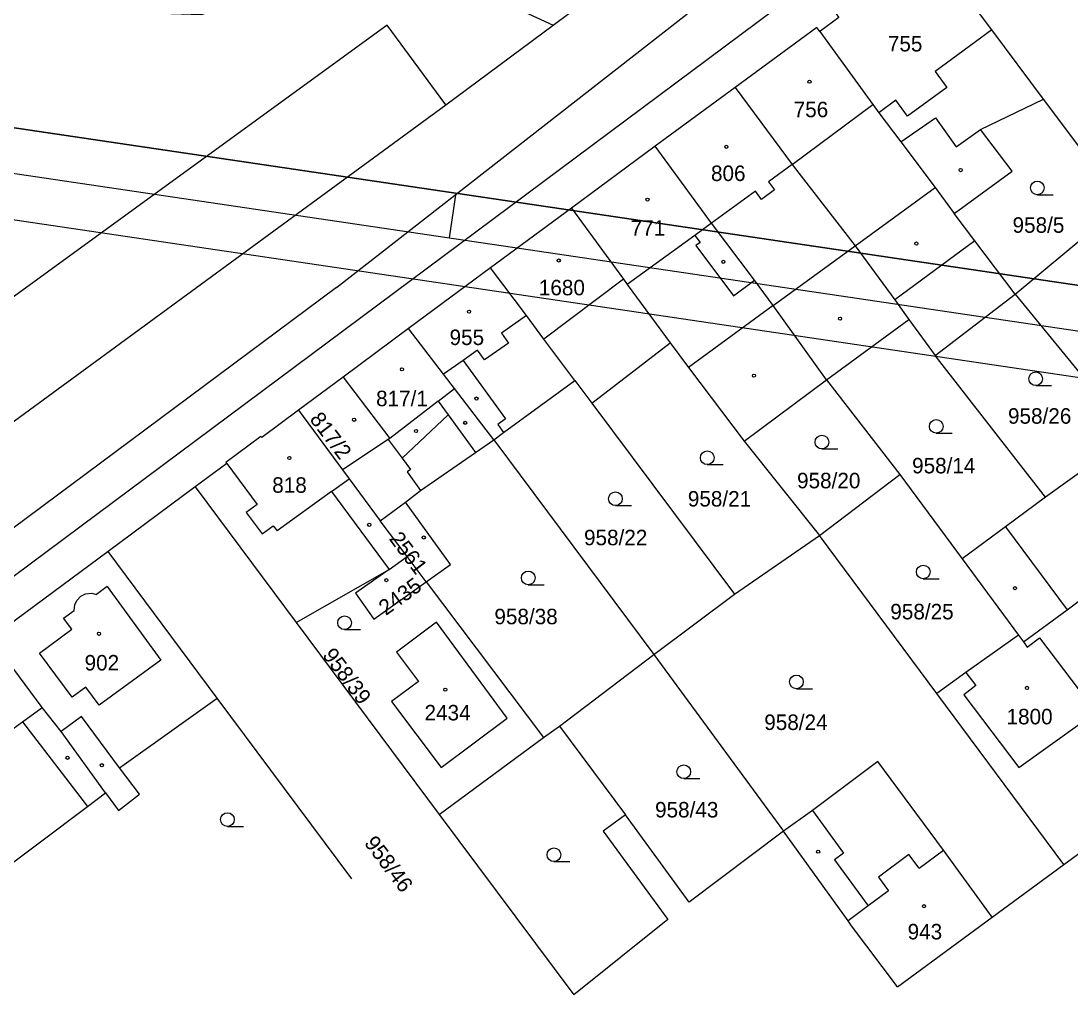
# Model space of a CAD drawing. Extents: x -779330 to -774454, y -1144748 to -1142831.
# Drawn here: x -775304.5 to -775189.2, y -1144676.5 to -1144569.6 of the extents above; entities that cross this region are included whole.
import ezdxf

# ---------------------------------------------------------------- set-up
doc = ezdxf.new("R2010")
doc.units = 0
for name, color, linetype in [('Hranice parcel', 7, 'Continuous'), ('Parcelní čísla', 7, 'Continuous'), ('Vnitřní kresba', 7, 'Continuous'), ('Vrstva 1', 7, 'Continuous'), ('Značky budov', 7, 'Continuous'), ('Značky kultur', 7, 'Continuous')]:
    doc.layers.add(name, color=color, linetype=linetype)

msp = doc.modelspace()

# ---------------------------------------------------------------- linework, layer by layer
at = {"layer": 'Hranice parcel'}
for p, q in [((-775226.12, -1144576.88), (-775234.89, -1144583.32)), ((-775183.58, -1144589.75), (-775192.26, -1144578.14)), ((-775234.89, -1144583.32), (-775244.08, -1144590.11)), ((-775244.08, -1144590.11), (-775252.95, -1144596.66)), ((-775195.38, -1144599.55), (-775183.58, -1144589.75)), ((-775252.95, -1144596.66), (-775261.98, -1144603.34)), ((-775204.14, -1144606.28), (-775195.38, -1144599.55)), ((-775195.38, -1144599.55), (-775182.64, -1144615.12)), ((-775216.06, -1144608.95), (-775207.02, -1144602.33)), ((-775207.02, -1144602.33), (-775204.14, -1144606.28)), ((-775261.98, -1144603.34), (-775269.14, -1144608.66)), ((-775241.83, -1144611.53), (-775233.23, -1144604.89)), ((-775192.04, -1144621.83), (-775204.14, -1144606.28)), ((-775269.14, -1144608.66), (-775274.06, -1144612.3)), ((-775225.1, -1144615.7), (-775216.06, -1144608.95)), ((-775216.06, -1144608.95), (-775208.02, -1144619.35)), ((-775243.69, -1144609.04), (-775241.83, -1144611.53)), ((-775241.83, -1144611.53), (-775226.16, -1144632.49)), ((-775252.61, -1144615.53), (-775235.02, -1144639.1)), ((-775225.1, -1144615.7), (-775216.86, -1144626.05)), ((-775182.64, -1144615.12), (-775192.04, -1144621.83)), ((-775216.86, -1144626.05), (-775208.02, -1144619.35)), ((-775208.02, -1144619.35), (-775201.17, -1144628.6)), ((-775285.39, -1144620.71), (-775294.95, -1144627.78)), ((-775285.39, -1144620.71), (-775274.29, -1144635.59)), ((-775262.29, -1144622.38), (-775260.65, -1144621.1)), ((-775265.07, -1144624.43), (-775262.29, -1144622.38)), ((-775262.11, -1144628.36), (-775265.07, -1144624.43)), ((-775226.16, -1144632.49), (-775216.86, -1144626.05)), ((-775294.95, -1144627.78), (-775307.84, -1144637.35)), ((-775282.98, -1144643.87), (-775294.95, -1144627.78)), ((-775264.09, -1144629.76), (-775262.11, -1144628.36)), ((-775260.03, -1144631.13), (-775262.11, -1144628.36)), ((-775201.17, -1144628.6), (-775195, -1144636.98)), ((-775274.29, -1144635.59), (-775264.09, -1144629.76)), ((-775260.03, -1144631.13), (-775247.14, -1144648.22)), ((-775235.02, -1144639.1), (-775226.16, -1144632.49)), ((-775274.29, -1144635.59), (-775258.59, -1144656.64)), ((-775245.38, -1144646.95), (-775235.02, -1144639.1)), ((-775235.02, -1144639.1), (-775220.81, -1144658.48)), ((-775268.2, -1144663.73), (-775282.98, -1144643.87)), ((-775247.14, -1144648.22), (-775245.38, -1144646.95)), ((-775245.38, -1144646.95), (-775238.16, -1144656.7)), ((-775258.59, -1144656.64), (-775247.14, -1144648.22)), ((-775295.23, -1144654.29), (-775293.79, -1144656.2)), ((-775190.02, -1144662.15), (-775181.13, -1144655.62)), ((-775258.59, -1144656.64), (-775243.82, -1144676.46)), ((-775231.17, -1144666.27), (-775238.16, -1144656.7)), ((-775220.81, -1144658.48), (-775231.17, -1144666.27)), ((-775197.9, -1144667.93), (-775190.02, -1144662.15)), ((-775208.3, -1144675.57), (-775197.9, -1144667.93))]:
    msp.add_line(p, q, dxfattribs=at)
for points in [[(-775376.32, -1144506.59), (-775360.11, -1144529.4), (-775362.24, -1144540.72), (-775355.95, -1144552.84), (-775351.38, -1144557.51), (-775330.85, -1144567.36), (-775284.69, -1144568.85), (-775263.45, -1144562.01), (-775246.07, -1144570.05)], [(-775246.07, -1144570.05), (-775235.05, -1144561.78), (-775230.93, -1144558.83), (-775228.56, -1144557.06)], [(-775192.26, -1144578.14), (-775197.93, -1144570.55), (-775204.58, -1144561.67), (-775206.63, -1144563.07), (-775206.87, -1144562.75)], [(-775206.87, -1144562.75), (-775215.07, -1144568.77), (-775214.74, -1144569.21), (-775216.8, -1144570.72)], [(-775318.59, -1144623.31), (-775317.85, -1144622.66), (-775257.86, -1144578.79), (-775246.07, -1144570.05)], [(-775216.8, -1144570.72), (-775217.13, -1144570.28), (-775226.12, -1144576.88)], [(-775216.8, -1144570.72), (-775211, -1144578.74), (-775210.33, -1144579.64), (-775207.91, -1144582.84), (-775204.14, -1144587.85), (-775202.06, -1144590.71)], [(-775226.12, -1144576.88), (-775219.86, -1144585.33), (-775219.74, -1144585.49), (-775212.93, -1144594.24), (-775208.59, -1144600.18), (-775207.02, -1144602.33)], [(-775202.06, -1144590.71), (-775195.7, -1144586.07), (-775199.16, -1144581.48), (-775192.26, -1144578.14)], [(-775216.06, -1144608.95), (-775221.92, -1144600.8), (-775224, -1144598.02), (-775228.69, -1144591.76), (-775234.89, -1144583.32)], [(-775244.08, -1144590.11), (-775238.38, -1144597.91), (-775237.95, -1144598.5), (-775233.23, -1144604.89)], [(-775195.38, -1144599.55), (-775199.8, -1144593.7), (-775202.06, -1144590.71)], [(-775243.69, -1144609.04), (-775247.1, -1144604.48), (-775249.03, -1144601.9), (-775252.95, -1144596.66)], [(-775252.61, -1144615.53), (-775256.93, -1144609.91), (-775258.13, -1144608.35), (-775261.98, -1144603.34)], [(-775233.23, -1144604.89), (-775231.24, -1144607.61), (-775225.1, -1144615.7)], [(-775269.14, -1144608.66), (-775264.03, -1144615.38), (-775264.2, -1144615.51), (-775262.68, -1144617.54), (-775261.74, -1144618.78), (-775262.1, -1144619.04), (-775260.65, -1144621.1)], [(-775252.61, -1144615.53), (-775251.53, -1144614.74), (-775243.69, -1144609.04)], [(-775274.06, -1144612.3), (-775278.08, -1144615.29), (-775278.17, -1144615.17), (-775282.02, -1144618.02), (-775281.93, -1144618.14), (-775285.39, -1144620.71)], [(-775274.06, -1144612.3), (-775269.2, -1144618.85), (-775268.48, -1144619.82), (-775265.07, -1144624.43)], [(-775260.65, -1144621.1), (-775254.61, -1144616.92), (-775252.61, -1144615.53)], [(-775260.03, -1144631.13), (-775257.35, -1144629.23), (-775262.29, -1144622.38)], [(-775192.04, -1144621.83), (-775196.41, -1144625.07), (-775201.17, -1144628.6)], [(-775190.02, -1144662.15), (-775203.97, -1144643.39), (-775216.86, -1144626.05)], [(-775195, -1144636.98), (-775194.46, -1144637.72), (-775189.64, -1144634.21), (-775185.64, -1144631.15), (-775181.27, -1144627.89), (-775181.15, -1144628.05)], [(-775264.09, -1144629.76), (-775267.78, -1144632.37), (-775265.79, -1144635.22), (-775260.03, -1144631.13)], [(-775263.82, -1144644.27), (-775258.38, -1144651.51), (-775251.12, -1144646.08), (-775258.88, -1144635.56), (-775263.27, -1144638.83), (-775260.87, -1144642.06), (-775263.82, -1144644.27)], [(-775295.23, -1144654.29), (-775300.12, -1144647.55), (-775302.19, -1144644.93), (-775307.84, -1144637.35)], [(-775195, -1144636.98), (-775200.79, -1144641.07), (-775199.69, -1144642.51), (-775201.01, -1144643.52), (-775194.95, -1144651.49), (-775188.01, -1144646.51), (-775187.72, -1144646.9), (-775181.13, -1144655.62)], [(-775293.79, -1144656.2), (-775291.52, -1144654.44), (-775293.69, -1144651.52), (-775282.98, -1144643.87)], [(-775197.9, -1144667.93), (-775203.23, -1144660.55), (-775210.44, -1144650.85), (-775217.63, -1144656.22), (-775220.81, -1144658.48)], [(-775308.02, -1144663.87), (-775297.21, -1144655.77), (-775295.23, -1144654.29)], [(-775238.16, -1144656.7), (-775240.59, -1144658.48), (-775233.51, -1144668.16), (-775243.82, -1144676.46)], [(-775208.3, -1144675.57), (-775213.32, -1144668.86), (-775213.71, -1144668.32), (-775220.81, -1144658.48)]]:
    msp.add_lwpolyline(points, dxfattribs=at)
at = {"layer": 'Vnitřní kresba'}
for p, q in [((-775269.86, -1144598.82), (-775222.72, -1144562.02)), ((-775219.39, -1144566.53), (-775352.58, -1144665.72)), ((-775264.3, -1144570.05), (-775317.98, -1144609.04)), ((-775257.86, -1144578.79), (-775264.3, -1144570.05)), ((-775197.93, -1144570.55), (-775204.16, -1144575.11)), ((-775204.16, -1144575.11), (-775202.86, -1144576.89)), ((-775202.86, -1144576.89), (-775207.18, -1144580.04)), ((-775219.86, -1144585.33), (-775211, -1144578.74)), ((-775208.47, -1144578.28), (-775210.33, -1144579.64)), ((-775207.18, -1144580.04), (-775208.47, -1144578.28)), ((-775207.91, -1144582.84), (-775204.12, -1144580.22)), ((-775204.12, -1144580.22), (-775201.85, -1144583.4)), ((-775201.85, -1144583.4), (-775199.16, -1144581.48)), ((-775219.86, -1144585.33), (-775222.45, -1144587.21)), ((-775221.8, -1144588.1), (-775223.23, -1144589.17)), ((-775222.45, -1144587.21), (-775221.8, -1144588.1)), ((-775212.93, -1144594.24), (-775204.14, -1144587.85)), ((-775223.89, -1144588.26), (-775228.69, -1144591.76)), ((-775223.23, -1144589.17), (-775223.89, -1144588.26)), ((-775228.69, -1144591.76), (-775230.52, -1144593.12)), ((-775230.52, -1144593.12), (-775237.95, -1144598.5)), ((-775230.52, -1144593.12), (-775229.96, -1144593.9)), ((-775229.96, -1144593.9), (-775230.41, -1144594.23)), ((-775199.8, -1144593.7), (-775208.59, -1144600.18)), ((-775230.41, -1144594.23), (-775226.29, -1144599.73)), ((-775221.92, -1144600.8), (-775212.93, -1144594.24)), ((-775238.38, -1144597.91), (-775247.1, -1144604.48)), ((-775226.29, -1144599.73), (-775224, -1144598.02)), ((-775269.86, -1144598.82), (-775328.21, -1144642.2)), ((-775221.92, -1144600.8), (-775231.24, -1144607.61)), ((-775249.03, -1144601.9), (-775251.76, -1144603.83)), ((-775251.76, -1144603.83), (-775250.98, -1144604.94)), ((-775250.98, -1144604.94), (-775253.64, -1144606.76)), ((-775254.39, -1144605.7), (-775255.97, -1144606.82)), ((-775253.64, -1144606.76), (-775254.39, -1144605.7)), ((-775255.97, -1144606.82), (-775258.13, -1144608.35)), ((-775255.97, -1144606.82), (-775251.31, -1144613.25)), ((-775258.71, -1144611.28), (-775256.93, -1144609.91)), ((-775258.71, -1144611.28), (-775264.03, -1144615.38)), ((-775258.71, -1144611.28), (-775257.6, -1144612.8)), ((-775257.6, -1144612.8), (-775262.68, -1144617.54)), ((-775257.6, -1144612.8), (-775254.61, -1144616.92)), ((-775251.31, -1144613.25), (-775252.16, -1144613.87)), ((-775252.16, -1144613.87), (-775251.53, -1144614.74)), ((-775264.2, -1144615.51), (-775269.2, -1144618.85)), ((-775281.93, -1144618.14), (-775278.57, -1144622.62)), ((-775270.43, -1144621.22), (-775268.48, -1144619.82)), ((-775270.43, -1144621.22), (-775276.4, -1144625.51)), ((-775270.43, -1144621.22), (-775264.09, -1144629.76)), ((-775278.57, -1144622.62), (-775279.79, -1144623.53)), ((-775279.79, -1144623.53), (-775278.03, -1144625.87)), ((-775278.03, -1144625.87), (-775276.81, -1144624.96)), ((-775276.81, -1144624.96), (-775276.4, -1144625.51)), ((-775196.41, -1144625.07), (-775189.64, -1144634.21)), ((-775295.07, -1144631.65), (-775296.22, -1144632.5)), ((-775295.07, -1144631.65), (-775289.15, -1144639.71)), ((-775298.61, -1144633.64), (-775298.37, -1144633.16)), ((-775298.37, -1144633.16), (-775297.94, -1144632.71)), ((-775297.94, -1144632.71), (-775297.42, -1144632.45)), ((-775297.42, -1144632.45), (-775296.75, -1144632.37)), ((-775296.75, -1144632.37), (-775296.22, -1144632.5)), ((-775299.83, -1144635.11), (-775298.69, -1144634.27)), ((-775298.69, -1144634.27), (-775298.61, -1144633.64)), ((-775298.94, -1144636.32), (-775299.83, -1144635.11)), ((-775302.49, -1144638.94), (-775298.94, -1144636.32)), ((-775194.46, -1144637.72), (-775194.05, -1144638.29)), ((-775194.05, -1144638.29), (-775192.71, -1144637.26)), ((-775192.71, -1144637.26), (-775186.51, -1144645.43)), ((-775298.91, -1144643.79), (-775302.49, -1144638.94)), ((-775289.15, -1144639.71), (-775295.93, -1144644.64)), ((-775200.79, -1144641.07), (-775203.97, -1144643.39)), ((-775297.39, -1144642.67), (-775298.91, -1144643.79)), ((-775295.93, -1144644.64), (-775297.39, -1144642.67)), ((-775304.35, -1144646.48), (-775302.19, -1144644.93)), ((-775310.13, -1144650.62), (-775304.35, -1144646.48)), ((-775304.35, -1144646.48), (-775297.21, -1144655.77)), ((-775297.86, -1144645.9), (-775300.12, -1144647.55)), ((-775293.69, -1144651.52), (-775297.86, -1144645.9)), ((-775217.63, -1144656.22), (-775214.21, -1144660.9)), ((-775205.92, -1144662.55), (-775203.23, -1144660.55)), ((-775214.21, -1144660.9), (-775215.21, -1144661.63)), ((-775215.21, -1144661.63), (-775211.51, -1144666.69)), ((-775207.03, -1144661.06), (-775210.36, -1144663.53)), ((-775205.92, -1144662.55), (-775207.03, -1144661.06)), ((-775210.36, -1144663.53), (-775209.26, -1144665.02)), ((-775209.26, -1144665.02), (-775211.51, -1144666.69)), ((-775211.51, -1144666.69), (-775213.71, -1144668.32))]:
    msp.add_line(p, q, dxfattribs=at)
at = {"layer": 'Vrstva 1'}
msp.add_line((-775256.78, -1144588.45), (-775257.51, -1144593.39), dxfattribs=at)
for points in [[(-774799.29, -1144366.04), (-776045.7, -1144181.56), (-776089.18, -1144475.34), (-774842.77, -1144659.83)], [(-774846.98, -1144654.15), (-776083.5, -1144471.13), (-776041.48, -1144187.23), (-774804.97, -1144370.25)], [(-774810.64, -1144374.46), (-775834.48, -1144222.92), (-775875.04, -1144496.94), (-774851.19, -1144648.48)], [(-774851.19, -1144648.48), (-775875.04, -1144496.94), (-775834.48, -1144222.92), (-774810.64, -1144374.46)]]:
    msp.add_lwpolyline(points, close=True, dxfattribs=at)
at = {"layer": 'Značky budov'}
for centre in [(-775217.94, -1144576.24), (-775227.08, -1144583.39), (-775201.35, -1144585.94), (-775235.73, -1144589.18), (-775206.21, -1144594), (-775245.47, -1144595.86), (-775227.41, -1144596.01), (-775255.32, -1144601.47), (-775214.59, -1144602.25), (-775262.69, -1144607.8), (-775224.04, -1144608.5), (-775254.5, -1144611.01), (-775267.94, -1144613.34), (-775255.75, -1144613.67), (-775261.14, -1144614.57), (-775275.05, -1144617.53), (-775266.28, -1144624.86), (-775260.29, -1144626.26), (-775264.4, -1144630.94), (-775195.38, -1144631.82), (-775295.95, -1144636.82), (-775257.93, -1144642.96), (-775194.06, -1144642.76), (-775299.41, -1144650.43), (-775295.64, -1144651.25), (-775216.99, -1144660.74), (-775205.38, -1144666.71)]:
    msp.add_circle(centre, 0.175, dxfattribs=at)
at = {"layer": 'Značky kultur'}
for p, q in [((-775192.93, -1144588.64), (-775191.18, -1144588.64)), ((-775193.11, -1144609.59), (-775191.36, -1144609.59)), ((-775204.03, -1144614.81), (-775202.28, -1144614.81)), ((-775216.58, -1144616.54), (-775214.83, -1144616.54)), ((-775229.17, -1144618.26), (-775227.42, -1144618.26)), ((-775239.25, -1144622.75), (-775237.5, -1144622.75)), ((-775205.46, -1144630.79), (-775203.71, -1144630.79)), ((-775248.83, -1144631.44), (-775247.08, -1144631.44)), ((-775268.99, -1144636.36), (-775267.24, -1144636.36)), ((-775219.38, -1144642.86), (-775217.63, -1144642.86)), ((-775231.75, -1144652.71), (-775230, -1144652.71)), ((-775281.85, -1144657.96), (-775280.1, -1144657.96)), ((-775246.01, -1144661.82), (-775244.26, -1144661.82))]:
    msp.add_line(p, q, dxfattribs=at)
for centre in [(-775192.93, -1144587.89), (-775193.11, -1144608.84), (-775204.03, -1144614.06), (-775216.58, -1144615.79), (-775229.17, -1144617.51), (-775239.25, -1144622), (-775205.46, -1144630.04), (-775248.83, -1144630.69), (-775268.99, -1144635.61), (-775219.38, -1144642.11), (-775231.75, -1144651.96), (-775281.85, -1144657.21), (-775246.01, -1144661.07)]:
    msp.add_circle(centre, 0.75, dxfattribs=at)

# ---------------------------------------------------------------- texts
at = {"layer": 'Parcelní čísla'}
for s, p in [('755', (-775209.34, -1144572.92)), ('756', (-775219.68, -1144580.14)), ('806', (-775228.76, -1144587.14)), ('771', (-775237.57, -1144593.14)), ('958/5', (-775195.65, -1144592.82)), ('1680', (-775247.66, -1144599.68)), ('955', (-775257.46, -1144605.14)), ('817/1', (-775265.53, -1144611.85)), ('958/26', (-775196.15, -1144613.77)), ('958/14', (-775206.68, -1144619.22)), ('958/20', (-775219.31, -1144620.86)), ('818', (-775276.93, -1144621.35)), ('958/21', (-775231.3, -1144622.86)), ('958/22', (-775242.7, -1144627.11)), ('958/38', (-775252.54, -1144635.78)), ('958/25', (-775209.07, -1144635.24)), ('902', (-775297.53, -1144640.85)), ('2434', (-775260.21, -1144646.33)), ('958/24', (-775222.91, -1144647.38)), ('1800', (-775196.31, -1144646.76)), ('958/43', (-775234.9, -1144656.98)), ('943', (-775207.17, -1144670.36))]:
    msp.add_text(s, height=1.7, dxfattribs=at).set_placement(p)
for s, rotation, p in [('817/2', 307, (-775272.89, -1144613.3)), ('2561', 307, (-775264.17, -1144626.42)), ('2435', 36, (-775264.45, -1144634.88)), ('958/39', 307, (-775271.49, -1144639.19)), ('958/46', 307, (-775266.9, -1144659.81))]:
    msp.add_text(s, height=1.7, rotation=rotation, dxfattribs=at).set_placement(p)

doc.saveas('drawing.dxf')
